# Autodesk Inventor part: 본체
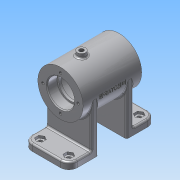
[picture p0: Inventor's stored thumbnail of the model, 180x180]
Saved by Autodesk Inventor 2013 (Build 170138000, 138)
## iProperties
Created: 2017-02
Part Number: 본체
Material: 알루미늄 6061
Document SubType Name: Modeling
Designer: Administrator
Mass: 356.083 g
Surface Area: 422.768 cm^2
Volume: 131.396 cm^3
Density: 2.71 g/cm^3
Author: Administrator
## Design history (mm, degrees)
sketch "스케치1"
  geometry: C1 r 27 at (0, 0); 1 further point
  constraints: 1 centre point, 1 coincident
  dimensions: "d0" = 54 diameter of C1
extrude "돌출1" new body sketch "스케치1" stored distance "d2" = 70; taper "d3" = 0 deg
sketch "스케치2"
  geometry: C1 r 27 at (0, 0) reference; C2 r 14 at (0, 0)
  constraints: 1 centre point, 1 coincident
  dimensions: "d4" = 28 diameter of C2
extrude "돌출2" cut sketch "스케치2" distance "d6" = 70; taper "d7" = 0 deg
sketch "스케치3"
  geometry: C1 r 14 at (0, 0) reference; C2 r 27 at (0, 0) reference; C3 r 16 at (0, 0)
  constraints: 1 centre point, 1 coincident
  dimensions: "d8" = 32 diameter of C3
extrude "돌출3" cut sketch "스케치3" distance "d10" = 12; taper "d11" = 0 deg
node "작업 평면1"
sketch "스케치4"
  geometry: C1 r 22 at (0, 0); 1 further point
  constraints: 1 centre point, 1 coincident
  dimensions: "d13" = 44 diameter of C1
extrude "돌출4" cut sketch "스케치4" distance "d15" = 40; taper "d16" = 0 deg
sketch "스케치5" dims "d17" = 42
  geometry: C1 r 16 at (0, 0) reference; C2 r 27 at (0, 0) reference; 2 further points
  constraints: 2 vertical alignment, 1 coincident, 2 other
hole "구멍1" sketch "스케치5" at (0, 21) diameter "d19" = 3.242; stored, may be unused: countersink angle "d23" = 90 deg, drill point angle "d25" = 118 deg; dims "d20" = 8, "d21" = 4, "d22" = 2, "d24" = 10
node "작업 평면2"
sketch "스케치6"
  geometry: L1 (27, 52)-(-27, 52); L2 (-27, 52)-(-27, 17); L3 (-27, 17)-(27, 17); L4 (27, 17)-(27, 52); L5 (27, -17)-(-27, -17); L6 (-27, -17)-(-27, -52); L7 (-27, -52)-(27, -52); L8 (27, -52)-(27, -17); 3 further points
  constraints: 16 end point, 4 parallel, 2 equal length, 2 horizontal, 2 midpoint, 2 perpendicular, 2 vertical alignment
  dimensions: "d30" = 17 distance from line of point (0, 0) L3; "d31" = 52 distance from line of L1 point (0, 0); "d32" = 54 distance of L1.start L1.end; "d33" = 17 distance from line of L5 point (0, 0)
extrude "돌출5" join sketch "스케치6" distance "d34" = 8; taper "d35" = 0 deg
fillet "모깎기1" dims "d36" = 10
sketch "스케치7"
  geometry: C1 r 2.5 at (17, -42); C2 r 2.5 at (-17, -42); C3 r 2.5 at (-17, 42); C4 r 2.5 at (17, 42); A1 r 10 centre (-17, -42) between (-27, -42) and (-17, -52) reference; A2 r 10 centre (17, -42) between (17, -52) and (27, -42) reference; 1 further point
  constraints: 4 centre point, 3 equal radius, 2 coincident, 2 vertical alignment, 1 horizontal alignment
  dimensions: "d37" = 5 diameter of C1; "d39" = 84 distance of C3.centre A1.centre
extrude "돌출6" cut sketch "스케치7" distance "d40" = 8; taper "d41" = 0 deg
sketch "스케치8"
  geometry: L1 (-12.5, -44.598)-(-17, -47.196); L2 (-17, -47.196)-(-21.5, -44.598); L3 (-21.5, -44.598)-(-21.5, -39.402); L4 (-21.5, -39.402)-(-17, -36.804); L5 (-17, -36.804)-(-12.5, -39.402); L6 (-12.5, -39.402)-(-12.5, -44.598); L7 (21.5, -44.598)-(17, -47.196); L8 (17, -47.196)-(12.5, -44.598); L9 (12.5, -44.598)-(12.5, -39.402); L10 (12.5, -39.402)-(17, -36.804); L11 (17, -36.804)-(21.5, -39.402); L12 (21.5, -39.402)-(21.5, -44.598); L13 (21.5, 39.402)-(17, 36.804); L14 (17, 36.804)-(12.5, 39.402); L15 (12.5, 39.402)-(12.5, 44.598); L16 (12.5, 44.598)-(17, 47.196); L17 (17, 47.196)-(21.5, 44.598); L18 (21.5, 44.598)-(21.5, 39.402); L19 (-12.5, 39.402)-(-17, 36.804); L20 (-17, 36.804)-(-21.5, 39.402); L21 (-21.5, 39.402)-(-21.5, 44.598); L22 (-21.5, 44.598)-(-17, 47.196); L23 (-17, 47.196)-(-12.5, 44.598); L24 (-12.5, 44.598)-(-12.5, 39.402); C1 r 2.5 at (17, -42) reference; C2 r 2.5 at (-17, -42) reference; C3 r 4.5 at (-17, -42); C4 r 4.5 at (17, -42); C5 r 4.5 at (17, 42); C6 r 4.5 at (-17, 42); A1 r 10 centre (-17, -42) between (-27, -42) and (-17, -52) reference; A2 r 10 centre (17, -42) between (17, -52) and (27, -42) reference; 5 further points
  constraints: 48 end point, 6 coincident, 4 centre point, 4 vertical, 3 equal radius, 3 tangent, 2 vertical alignment, 1 horizontal alignment, 1 parallel, 52 other
  dimensions: "d42" = 84 distance of C2.centre point (-17, 42); "d43" = 9 diameter of C6
extrude "돌출7" cut sketch "스케치8" distance "d44" = 3; taper "d45" = 0 deg
sketch "스케치9"
  geometry: L1 (27, -42)-(27, -17) reference; L2 (-27, -17)-(27, -17); L3 (27, -17)-(27, -25); L4 (27, -25)-(-27, -25); L5 (-27, -25)-(-27, -17); L6 (-27, 17)-(27, 17) reference; L7 (27, 17)-(27, 42) reference; L8 (-27, 17)-(27, 17); L9 (27, 17)-(27, 25); L10 (27, 25)-(-27, 25); L11 (-27, 25)-(-27, 17); 1 further point
  constraints: 16 end point, 4 parallel, 2 horizontal, 2 perpendicular, 2 point on line
  dimensions: "d46" = 8 distance between parallel lines of L2 L4; "d48" = 8 distance between parallel lines of L10 L8
extrude "돌출8" join sketch "스케치9" stored distance "d49" = 3; taper "d50" = 0 deg
node "작업 평면3"
sketch "스케치10"
  geometry: L1 (27, 35)-(-27, 35) reference; C1 r 5 at (0, 10); 1 further point
  constraints: 1 centre point, 1 vertical alignment
  dimensions: "d52" = 25 distance from line of C1.centre L1; "d53" = 10 diameter of C1
extrude "돌출9" join sketch "스케치10" stored distance "d54" = 3; taper "d55" = 0 deg
sketch "스케치11"
  geometry: C1 r 5 at (0, 0) reference; 2 further points
  constraints: 1 coincident
hole "구멍2" sketch "스케치11" at (0, 0) diameter "d56" = 5.188; stored, may be unused: countersink angle "d60" = 90 deg, drill point angle "d62" = 118 deg; dims "d57" = 8, "d58" = 4, "d59" = 2, "d61" = 10
sketch "스케치12"
  geometry: L1 (0, 0)-(-16.339, -25.16); L2 (0, 0)-(0, -27); A1 r 27 centre (0, 0) between (-27, 0) and (27, 0) reference
  constraints: 4 end point, 1 point on circle
  dimensions: "d63" = 33 deg angle of L1 L2; "d64" = 30 distance of L1.start L1.end
node "작업 평면4"
sketch "스케치13"
  geometry: C1 r 6 at (0, 0); 1 further point
  constraints: 1 centre point, 1 coincident
  dimensions: "d65" = 12 diameter of C1
extrude "돌출10" join sketch "스케치13" stored distance "d67" = 3; taper "d68" = 0 deg
sketch "스케치14"
  geometry: C1 r 6 at (0, 0) reference; 1 further point
  constraints: 1 coincident
hole "구멍3" sketch "스케치14" at (0, 0) diameter "d69" = 5.188; stored, may be unused: countersink angle "d73" = 90 deg, drill point angle "d75" = 118 deg; dims "d70" = 8, "d71" = 4, "d72" = 2, "d74" = 10
node "작업 평면5"
sketch "스케치15"
  geometry: L1 (27, 35)-(-27, 35) reference; L2 (27, -35)-(27, 35) reference; 2 further points
  constraints: 1 other
  dimensions: "d77" = 35 distance from line of L1 point (0, 0); "d78" = 27 distance from line of point (0, 0) L2
feature "엠보싱1" sketch "스케치15" dims "d0" = 54, "d79" = 0.5, "d80" = 0
chamfer "모따기1" distance "d81" = 1; stored, may be unused: second distance "d82" = 2, angle "d83" = 45 deg
fillet "모깎기2" dims "d84" = 0.3
fillet "모깎기3" dims "d85" = 3
fillet "모깎기4" dims "d86" = 2
fillet "모깎기5" dims "d87" = 2
fillet "모깎기6" dims "d88" = 2
fillet "모깎기7" dims "d89" = 2
fillet "모깎기8" dims "d90" = 2
fillet "모깎기9" dims "d91" = 2
fillet "모깎기10" dims "d92" = 2
node "솔리드1"
pattern_circular "원형 패턴1" dims angle "d27" = 360 deg
mirror "대칭1"
other parameters: "d12" = -15, "d51" = -92, "d76" = 63
